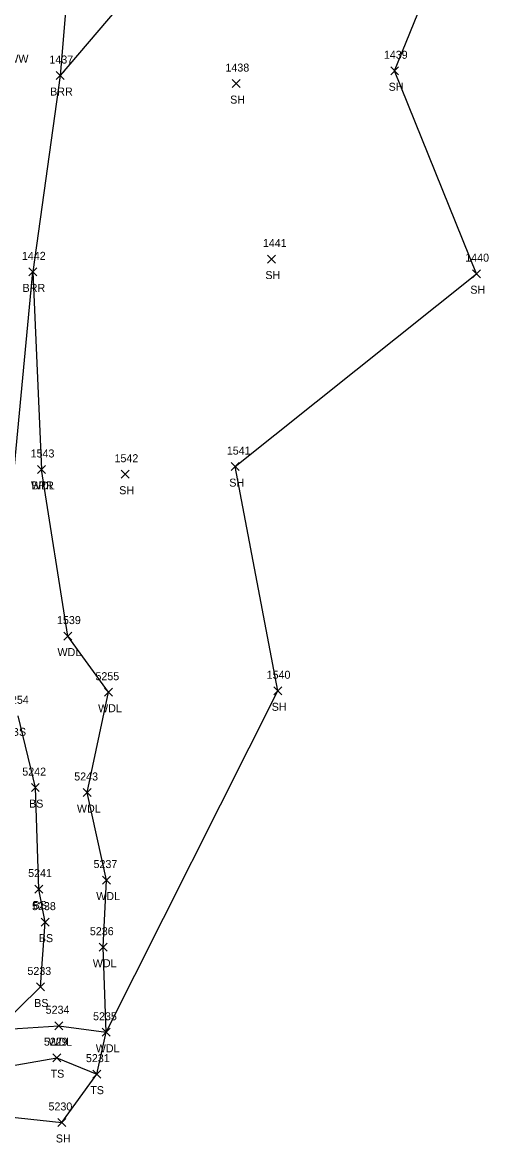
# Model space of a CAD drawing. Extents: x 1509053 to 1511576, y 400838 to 402572.
# Drawn here: x 1509791.5 to 1509908.1, y 401143.5 to 401423.4 of the extents above; entities that cross this region are included whole.
import ezdxf

# ---------------------------------------------------------------- set-up
doc = ezdxf.new("R2010")
doc.units = 0
for name, color, linetype in [('L_A', 7, 'Continuous'), ('L_I', 7, 'Continuous'), ('L_TIC', 7, 'Continuous'), ('LABL', 7, 'Continuous'), ('LAWA', 7, 'Continuous'), ('LELB', 7, 'Continuous'), ('LSOGP', 7, 'Continuous')]:
    doc.layers.add(name, color=color, linetype=linetype)

msp = doc.modelspace()

# ---------------------------------------------------------------- linework, layer by layer
at = {"layer": 'L_TIC'}
for points in [[(1509883.64, 401410.27), (1509885.64, 401412.27)], [(1509885.64, 401410.27), (1509883.64, 401412.27)], [(1509799.98, 401409.08), (1509801.98, 401411.08)], [(1509801.98, 401409.08), (1509799.98, 401411.08)], [(1509844.01, 401407.07), (1509846.01, 401409.07)], [(1509846.01, 401407.07), (1509844.01, 401409.07)], [(1509852.81, 401363.24), (1509854.81, 401365.24)], [(1509854.81, 401363.24), (1509852.81, 401365.24)], [(1509793.11, 401360.03), (1509795.11, 401362.03)], [(1509795.11, 401360.03), (1509793.11, 401362.03)], [(1509904.07, 401359.58), (1509906.07, 401361.58)], [(1509906.07, 401359.58), (1509904.07, 401361.58)], [(1509843.79, 401311.38), (1509845.79, 401313.38)], [(1509845.79, 401311.38), (1509843.79, 401313.38)], [(1509795.29, 401310.68), (1509797.28, 401312.68)], [(1509797.28, 401310.68), (1509795.29, 401312.68)], [(1509795.29, 401310.68), (1509797.28, 401312.68)], [(1509797.28, 401310.68), (1509795.29, 401312.68)], [(1509816.26, 401309.48), (1509818.26, 401311.48)], [(1509818.26, 401309.48), (1509816.26, 401311.48)], [(1509801.89, 401269.04), (1509803.89, 401271.04)], [(1509803.89, 401269.04), (1509801.89, 401271.04)], [(1509812.05, 401255.02), (1509814.05, 401257.02)], [(1509814.05, 401255.02), (1509812.05, 401257.02)], [(1509854.4, 401255.38), (1509856.4, 401257.38)], [(1509856.4, 401255.38), (1509854.4, 401257.38)], [(1509793.77, 401231.19), (1509795.77, 401233.19)], [(1509795.77, 401231.19), (1509793.77, 401233.19)], [(1509806.76, 401229.97), (1509808.76, 401231.97)], [(1509808.76, 401229.97), (1509806.76, 401231.97)], [(1509811.58, 401208.09), (1509813.58, 401210.09)], [(1509813.58, 401208.09), (1509811.58, 401210.09)], [(1509794.66, 401205.85), (1509796.66, 401207.85)], [(1509796.66, 401205.85), (1509794.66, 401207.85)], [(1509796.2, 401197.58), (1509798.2, 401199.58)], [(1509798.2, 401197.58), (1509796.2, 401199.58)], [(1509810.72, 401191.32), (1509812.72, 401193.32)], [(1509812.72, 401191.32), (1509810.72, 401193.32)], [(1509795.05, 401181.39), (1509797.05, 401183.39)], [(1509797.05, 401181.39), (1509795.05, 401183.39)], [(1509799.61, 401171.7), (1509801.61, 401173.7)], [(1509801.61, 401171.7), (1509799.61, 401173.7)], [(1509811.47, 401170.07), (1509813.47, 401172.07)], [(1509813.47, 401170.07), (1509811.47, 401172.07)], [(1509799.18, 401163.72), (1509801.18, 401165.72)], [(1509801.18, 401163.72), (1509799.18, 401165.72)], [(1509809.11, 401159.61), (1509811.11, 401161.61)], [(1509811.11, 401159.61), (1509809.11, 401161.61)], [(1509800.41, 401147.54), (1509802.41, 401149.54)], [(1509802.41, 401147.54), (1509800.41, 401149.54)]]:
    msp.add_lwpolyline(points, dxfattribs=at)
at = {"layer": 'LABL'}
msp.add_lwpolyline([(1509804.43, 401450.94), (1509800.98, 401410.08), (1509794.11, 401361.03), (1509796.28, 401311.67)], dxfattribs=at)
at = {"layer": 'LAWA'}
for points in [[(1509802.89, 401270.04), (1509796.28, 401311.67)], [(1509813.05, 401256.02), (1509802.89, 401270.04)], [(1509743.31, 401158.76), (1509753.29, 401169), (1509772.78, 401167.81), (1509783.4, 401161.76), (1509785.08, 401171.7), (1509800.61, 401172.7), (1509812.47, 401171.07), (1509811.72, 401192.32), (1509812.58, 401209.09), (1509807.76, 401230.97), (1509813.05, 401256.02)]]:
    msp.add_lwpolyline(points, dxfattribs=at)
at = {"layer": 'LELB'}
for points in [[(1509839.19, 401454.9), (1509800.98, 401410.08)], [(1509784.91, 401263.98), (1509794.11, 401361.03)], [(1509785.08, 401171.7), (1509796.05, 401182.39), (1509797.2, 401198.58), (1509795.66, 401206.85), (1509794.77, 401232.19), (1509790.44, 401250.12)], [(1509783.4, 401161.76), (1509800.18, 401164.72), (1509810.11, 401160.61)]]:
    msp.add_lwpolyline(points, dxfattribs=at)
at = {"layer": 'LSOGP'}
msp.add_lwpolyline([(1509779.68, 401150.88), (1509801.41, 401148.54), (1509810.11, 401160.61), (1509812.47, 401171.07), (1509855.4, 401256.38), (1509844.79, 401312.38), (1509905.07, 401360.58), (1509884.64, 401411.27), (1509903.2, 401456.94)], dxfattribs=at)

# ---------------------------------------------------------------- texts
at = {"layer": 'L_A'}
for s, p in [('FNWW', (1509784.44, 401413.27)), ('BRR', (1509798.47, 401405.08)), ('SH', (1509883.13, 401406.27)), ('SH', (1509843.5, 401403.07)), ('SH', (1509852.3, 401359.24)), ('BRR', (1509791.59, 401356.03)), ('SH', (1509903.56, 401355.58)), ('WDL', (1509793.7, 401306.67)), ('BRR', (1509793.77, 401306.67)), ('SH', (1509843.28, 401307.38)), ('SH', (1509815.75, 401305.48)), ('WDL', (1509800.31, 401265.04)), ('WDL', (1509810.47, 401251.02)), ('SH', (1509853.89, 401251.38)), ('BS', (1509788.89, 401245.12)), ('BS', (1509793.21, 401227.19)), ('WDL', (1509805.17, 401225.97)), ('WDL', (1509810, 401204.09)), ('BS', (1509794.1, 401201.85)), ('BS', (1509795.64, 401193.58)), ('WDL', (1509809.14, 401187.32)), ('BS', (1509794.49, 401177.39)), ('WDL', (1509798.03, 401167.7)), ('WDL', (1509809.89, 401166.07)), ('TS', (1509798.59, 401159.72)), ('TS', (1509808.52, 401155.61)), ('SH', (1509799.9, 401143.54))]:
    msp.add_text(s, height=2, dxfattribs=at).set_placement(p)
at = {"layer": 'L_I'}
for s, p in [('1437', (1509798.29, 401413.08)), ('1439', (1509881.94, 401414.27)), ('1438', (1509842.32, 401411.07)), ('1441', (1509851.68, 401367.24)), ('1442', (1509791.41, 401364.03)), ('1440', (1509902.29, 401363.58)), ('1543', (1509793.59, 401314.67)), ('1543', (1509793.59, 401314.67)), ('1541', (1509842.66, 401315.38)), ('1542', (1509814.57, 401313.48)), ('1539', (1509800.19, 401273.04)), ('5255', (1509809.8, 401259.02)), ('1540', (1509852.62, 401259.38)), ('5254', (1509787.18, 401253.12)), ('5242', (1509791.51, 401235.19)), ('5243', (1509804.5, 401233.97)), ('5237', (1509809.32, 401212.09)), ('5241', (1509792.97, 401209.85)), ('5238', (1509793.94, 401201.58)), ('5236', (1509808.41, 401195.32)), ('5233', (1509792.79, 401185.39)), ('5234', (1509797.35, 401175.7)), ('5235', (1509809.21, 401174.07)), ('5229', (1509796.91, 401167.72)), ('5231', (1509807.42, 401163.61)), ('5230', (1509798.06, 401151.54))]:
    msp.add_text(s, height=2, dxfattribs=at).set_placement(p)

doc.saveas('drawing.dxf')
